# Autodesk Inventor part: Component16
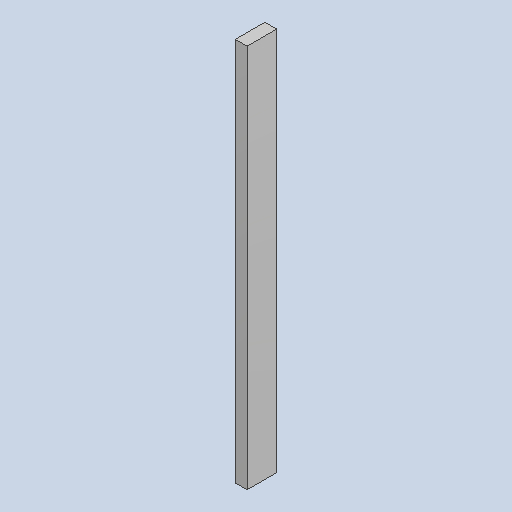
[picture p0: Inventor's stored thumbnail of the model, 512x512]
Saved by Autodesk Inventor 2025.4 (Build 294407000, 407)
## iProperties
Created: 2026-06
Part Number: Component16
Material: Generic
Document SubType Name: Modeling
Designer: AdminForWorker
Density: 1 g/cm^3
Appearance: Default
Title: Component16
Author: AdminForWorker
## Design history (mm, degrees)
feature "Body1"
body "Solid1"
